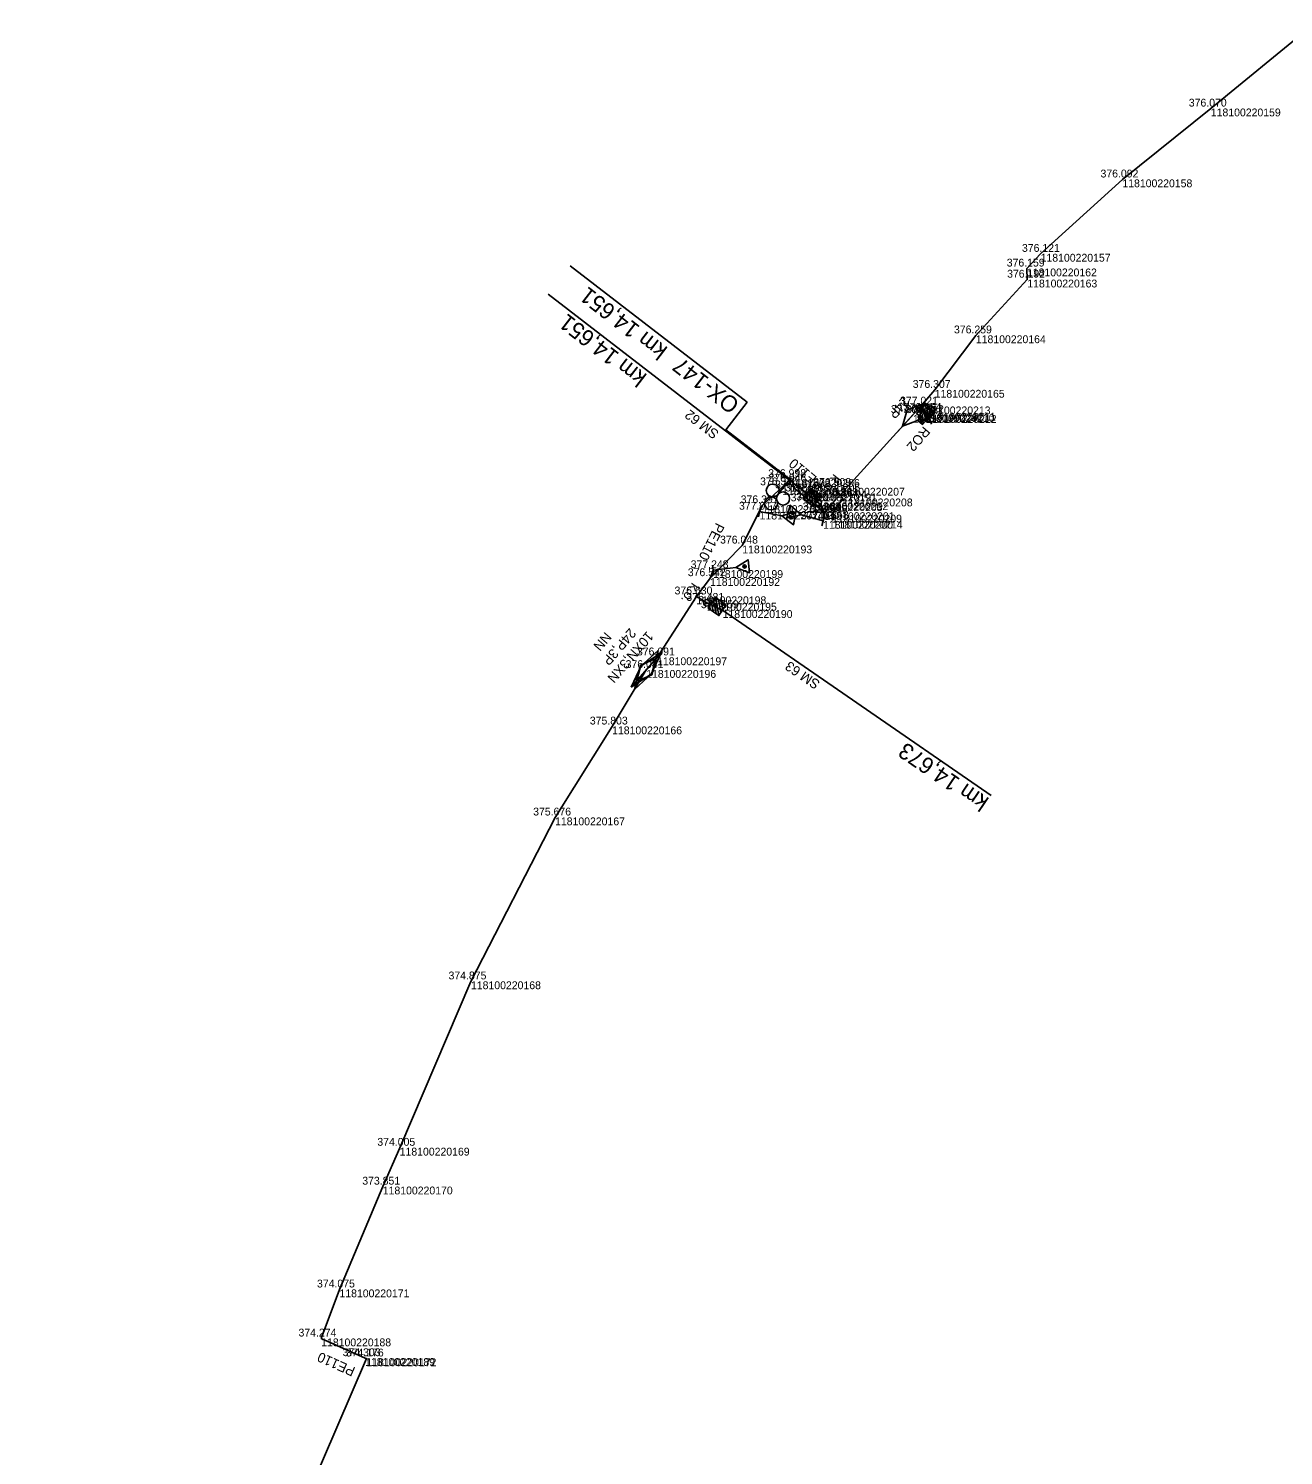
# Model space of a CAD drawing. Extents: x -732194 to -724760, y -944826 to -941477.
# Drawn here: x -730936.3 to -730744.2, y -941838.8 to -941620.2 of the extents above; entities that cross this region are included whole.
import ezdxf

# ---------------------------------------------------------------- set-up
doc = ezdxf.new("R2010")
doc.units = 0
for name, color, linetype in [('Vrstva 17', 7, 'Continuous'), ('Vrstva 25', 7, 'Continuous'), ('Vrstva 26', 7, 'Continuous'), ('Vrstva 28', 7, 'Continuous'), ('Vrstva 3', 7, 'Continuous'), ('Vrstva 31', 7, 'Continuous'), ('Vrstva 33', 7, 'Continuous'), ('Vrstva 35', 7, 'Continuous'), ('Vrstva 36', 7, 'Continuous'), ('Vrstva 4', 7, 'Continuous'), ('Vrstva 60', 7, 'Continuous'), ('Vrstva 61', 7, 'Continuous'), ('Vrstva 8', 7, 'Continuous')]:
    doc.layers.add(name, color=color, linetype=linetype)

msp = doc.modelspace()

# ---------------------------------------------------------------- linework, layer by layer
at = {"layer": 'Vrstva 17'}
msp.add_lwpolyline([(-730812.87, -941690.59), (-730811.67, -941692.23), (-730813.31, -941694.71), (-730813.21, -941695.61)], dxfattribs=at)
at = {"layer": 'Vrstva 25'}
msp.add_lwpolyline([(-730798.84, -941678.21), (-730798.08, -941678.86), (-730799.39, -941680.38), (-730800.15, -941679.72), (-730798.84, -941678.21)], dxfattribs=at)
at = {"layer": 'Vrstva 26'}
for points in [[(-730799.12, -941679.29), (-730799.74, -941678.13), (-730800.92, -941679.43), (-730814.44, -941694.33), (-730816.29, -941692.95), (-730818.68, -941690.96), (-730819.69, -941689.96), (-730820.94, -941690.5), (-730823.94, -941693.25), (-730827.05, -941699.43), (-730831.98, -941704.42), (-730834.08, -941707.22), (-730840.09, -941716.56), (-730841.76, -941718.5), (-730846.98, -941727.15), (-730855.72, -941741.09), (-730868.59, -941766.2), (-730879.51, -941791.69), (-730882.1, -941797.64), (-730888.73, -941813.4), (-730891.53, -941820.91), (-730884.81, -941823.92), (-730884.6, -941823.97), (-730893.54, -941844.74)], [(-730839.95, -941715.5), (-730840.91, -941719.02), (-730843.57, -941721.5), (-730842.62, -941717.98), (-730839.95, -941715.5)]]:
    msp.add_lwpolyline(points, dxfattribs=at)
at = {"layer": 'Vrstva 28'}
for p, q in [((-730798.58, -941676.84), (-730803.27, -941682.02)), ((-730801.79, -941678.65), (-730799.36, -941677.71)), ((-730799.36, -941677.71), (-730800.06, -941680.21)), ((-730802.49, -941681.15), (-730801.79, -941678.65)), ((-730800.06, -941680.21), (-730802.49, -941681.15)), ((-730800.16, -941680.16), (-730800.15, -941680.26)), ((-730799.8, -941679.77), (-730799.76, -941680.62)), ((-730799.74, -941678.13), (-730798.82, -941679.44)), ((-730799.44, -941679.38), (-730799.37, -941680.79)), ((-730799.09, -941678.98), (-730799.02, -941680.4)), ((-730798.73, -941678.59), (-730798.66, -941680)), ((-730798.37, -941678.2), (-730798.31, -941679.61)), ((-730798, -941678.16), (-730797.95, -941679.22)), ((-730797.61, -941678.52), (-730797.59, -941678.82)), ((-730819.69, -941689.96), (-730819.76, -941689.24)), ((-730823.94, -941693.25), (-730824.4, -941694.24)), ((-730815.39, -941692.77), (-730815.45, -941692.85)), ((-730814.44, -941694.33), (-730814.68, -941695.66)), ((-730831.98, -941704.42), (-730831.51, -941703.2)), ((-730832.44, -941708.17), (-730832.5, -941708.25)), ((-730844.04, -941721.15), (-730839.49, -941715.85)), ((-730842.64, -941717.74), (-730840.24, -941716.74)), ((-730840.24, -941716.74), (-730840.88, -941719.26)), ((-730843.28, -941720.27), (-730842.64, -941717.74)), ((-730840.88, -941719.26), (-730843.28, -941720.27))]:
    msp.add_line(p, q, dxfattribs=at)
for points in [[(-730814.44, -941694.33), (-730800.92, -941679.43), (-730799.74, -941678.13), (-730797.58, -941675.58), (-730791.28, -941667.23), (-730783.4, -941658.69), (-730783.46, -941656.99), (-730781.36, -941654.74), (-730768.84, -941643.34), (-730755.3, -941632.48), (-730740.34, -941620.23)], [(-730797.38, -941680.08), (-730798.45, -941679.77), (-730798.05, -941680.82)], [(-730834.08, -941707.22), (-730831.98, -941704.42), (-730827.05, -941699.43), (-730823.94, -941693.25), (-730820.94, -941690.5), (-730819.69, -941689.96), (-730818.68, -941690.96), (-730816.29, -941692.95), (-730814.44, -941694.33)], [(-730814.44, -941694.33), (-730815.42, -941692.81), (-730817.14, -941691.45)], [(-730936.34, -941912.8), (-730933.6, -941909.47), (-730918.42, -941890.11), (-730909.51, -941875.76), (-730901.25, -941861.12), (-730893.54, -941844.74), (-730884.6, -941823.97), (-730884.81, -941823.92), (-730891.53, -941820.91), (-730888.73, -941813.4), (-730882.1, -941797.64), (-730879.51, -941791.69), (-730868.59, -941766.2), (-730855.72, -941741.09), (-730846.98, -941727.15), (-730841.76, -941718.5), (-730840.09, -941716.56), (-730834.08, -941707.22), (-730832.47, -941708.21), (-730830.06, -941709.33)]]:
    msp.add_lwpolyline(points, dxfattribs=at)
msp.add_lwpolyline([(-730797.45, -941678.66), (-730799.46, -941680.88), (-730800.2, -941680.21), (-730798.19, -941677.99)], close=True, dxfattribs=at)
for centre in [(-730815.42, -941692.81), (-730832.47, -941708.21)]:
    msp.add_circle(centre, 0.5, dxfattribs=at)
at = {"layer": 'Vrstva 3'}
for p, q in [((-730856.75, -941660.93), (-730817.14, -941691.45)), ((-730816.59, -941693.14), (-730816.86, -941691.08)), ((-730816.17, -941693.47), (-730816.53, -941690.66)), ((-730815.85, -941693.05), (-730816.11, -941690.99)), ((-730817.43, -941692.5), (-730817.5, -941691.92)), ((-730817.01, -941692.82), (-730817.18, -941691.5)), ((-730815.52, -941692.63), (-730815.69, -941691.31)), ((-730815.2, -941692.21), (-730815.27, -941691.63)), ((-730831.75, -941708.26), (-730831.5, -941709.56)), ((-730831.45, -941707.82), (-730831.06, -941709.86)), ((-730831.15, -941707.38), (-730830.62, -941710.16)), ((-730830.71, -941707.68), (-730830.32, -941709.72)), ((-730830.27, -941707.98), (-730830.02, -941709.28)), ((-730829.83, -941708.27), (-730829.73, -941708.84)), ((-730832.04, -941708.7), (-730831.94, -941709.27)), ((-730788.92, -941737.75), (-730830.06, -941709.33))]:
    msp.add_line(p, q, dxfattribs=at)
for points in [[(-730817.75, -941692.25), (-730816.53, -941690.66), (-730814.95, -941691.88), (-730816.17, -941693.47)], [(-730829.5, -941708.5), (-730830.62, -941710.16), (-730832.27, -941709.04), (-730831.15, -941707.38)]]:
    msp.add_lwpolyline(points, close=True, dxfattribs=at)
at = {"layer": 'Vrstva 31'}
for points in [[(-730740.34, -941620.23), (-730755.3, -941632.48), (-730768.84, -941643.34), (-730781.36, -941654.74), (-730783.46, -941656.99), (-730783.4, -941658.69), (-730791.28, -941667.23), (-730797.58, -941675.58), (-730799.74, -941678.13), (-730798.95, -941679.08)], [(-730799.74, -941678.13), (-730800.92, -941679.43), (-730814.44, -941694.33), (-730816.29, -941692.95), (-730818.68, -941690.96), (-730819.69, -941689.96), (-730820.94, -941690.5), (-730823.94, -941693.25), (-730827.05, -941699.43), (-730831.98, -941704.42), (-730834.08, -941707.22), (-730840.09, -941716.56), (-730841.76, -941718.5), (-730846.98, -941727.15), (-730855.72, -941741.09), (-730868.59, -941766.2), (-730879.51, -941791.69), (-730882.1, -941797.64), (-730888.73, -941813.4), (-730891.53, -941820.91), (-730884.81, -941823.92), (-730884.6, -941823.97), (-730893.54, -941844.74)], [(-730844.04, -941721.15), (-730842.52, -941717.85), (-730839.48, -941715.85), (-730841, -941719.15), (-730844.04, -941721.15)]]:
    msp.add_lwpolyline(points, dxfattribs=at)
at = {"layer": 'Vrstva 33'}
for p, q in [((-730798.57, -941679.41), (-730799.33, -941678.76)), ((-730798.24, -941679.03), (-730798.9, -941679.79))]:
    msp.add_line(p, q, dxfattribs=at)
msp.add_lwpolyline([(-730797.54, -941678.98), (-730798.85, -941680.5), (-730800.36, -941679.19), (-730799.05, -941677.67), (-730797.54, -941678.98)], dxfattribs=at)
at = {"layer": 'Vrstva 35'}
for p, q in [((-730818.68, -941690.96), (-730816.29, -941692.95)), ((-730891.53, -941820.91), (-730884.81, -941823.92))]:
    msp.add_line(p, q, dxfattribs=at)
msp.add_lwpolyline([(-730831.98, -941704.42), (-730827.05, -941699.43), (-730823.94, -941693.25), (-730820.94, -941690.5)], dxfattribs=at)
at = {"layer": 'Vrstva 4'}
for p, q in [((-730824.25, -941693.48), (-730824.55, -941695.01)), ((-730819.77, -941694.91), (-730819.5, -941695.31)), ((-730819.24, -941694.63), (-730819.48, -941694.21)), ((-730814.88, -941696.41), (-730814.47, -941694.91)), ((-730831.59, -941702.42), (-730831.42, -941703.97)), ((-730826.89, -941702.48), (-730826.51, -941702.79))]:
    msp.add_line(p, q, dxfattribs=at)
for points in [[(-730814.68, -941695.66), (-730818.03, -941694.75), (-730820.23, -941695.18), (-730819.71, -941693.25), (-730818.03, -941694.75)], [(-730824.4, -941694.24), (-730820.98, -941694.89), (-730818.83, -941694.29), (-730819.19, -941696.25), (-730820.98, -941694.89)], [(-730831.51, -941703.2), (-730828.05, -941702.82), (-730826.16, -941701.62), (-730825.94, -941703.6), (-730828.05, -941702.82)]]:
    msp.add_lwpolyline(points, dxfattribs=at)
for centre in [(-730819.64, -941695.11), (-730819.36, -941694.42), (-730826.7, -941702.64)]:
    msp.add_circle(centre, 0.248, dxfattribs=at)
at = {"layer": 'Vrstva 60'}
for p, q in [((-730755.3, -941632.48), (-730755.3, -941632.48)), ((-730768.84, -941643.34), (-730768.84, -941643.34)), ((-730781.36, -941654.74), (-730781.36, -941654.74)), ((-730783.46, -941656.99), (-730783.46, -941656.99)), ((-730783.4, -941658.69), (-730783.4, -941658.69)), ((-730791.28, -941667.23), (-730791.28, -941667.23)), ((-730797.58, -941675.58), (-730797.58, -941675.58)), ((-730800.92, -941679.43), (-730800.92, -941679.43)), ((-730799.74, -941678.13), (-730799.74, -941678.13)), ((-730799.12, -941679.29), (-730799.12, -941679.29)), ((-730798.95, -941679.08), (-730798.95, -941679.08)), ((-730798.82, -941679.44), (-730798.82, -941679.44)), ((-730820.94, -941690.5), (-730820.94, -941690.5)), ((-730819.76, -941689.24), (-730819.76, -941689.24)), ((-730819.69, -941689.96), (-730819.69, -941689.96)), ((-730818.68, -941690.96), (-730818.68, -941690.96)), ((-730812.87, -941690.59), (-730812.87, -941690.59)), ((-730823.94, -941693.25), (-730823.94, -941693.25)), ((-730817.14, -941691.45), (-730817.14, -941691.45)), ((-730816.29, -941692.95), (-730816.29, -941692.95)), ((-730815.42, -941692.81), (-730815.42, -941692.81)), ((-730811.67, -941692.23), (-730811.67, -941692.23)), ((-730824.4, -941694.24), (-730824.4, -941694.24)), ((-730814.44, -941694.33), (-730814.44, -941694.33)), ((-730813.31, -941694.71), (-730813.31, -941694.71)), ((-730814.68, -941695.66), (-730814.68, -941695.66)), ((-730813.21, -941695.61), (-730813.21, -941695.61)), ((-730827.05, -941699.43), (-730827.05, -941699.43)), ((-730831.51, -941703.2), (-730831.51, -941703.2)), ((-730831.98, -941704.42), (-730831.98, -941704.42)), ((-730834.08, -941707.22), (-730834.08, -941707.22)), ((-730832.47, -941708.21), (-730832.47, -941708.21)), ((-730830.06, -941709.33), (-730830.06, -941709.33)), ((-730840.09, -941716.56), (-730840.09, -941716.56)), ((-730841.76, -941718.5), (-730841.76, -941718.5)), ((-730846.98, -941727.15), (-730846.98, -941727.15)), ((-730855.72, -941741.09), (-730855.72, -941741.09)), ((-730868.59, -941766.2), (-730868.59, -941766.2)), ((-730879.51, -941791.69), (-730879.51, -941791.69)), ((-730882.1, -941797.64), (-730882.1, -941797.64)), ((-730888.73, -941813.4), (-730888.73, -941813.4)), ((-730891.53, -941820.91), (-730891.53, -941820.91)), ((-730884.81, -941823.92), (-730884.81, -941823.92)), ((-730884.6, -941823.97), (-730884.6, -941823.97))]:
    msp.add_line(p, q, dxfattribs=at)
at = {"layer": 'Vrstva 8'}
for p, q in [((-730853.38, -941656.56), (-730826.28, -941677.45)), ((-730819.17, -941689.7), (-730820.36, -941688.79)), ((-730819.76, -941689.24), (-730821.59, -941691.62))]:
    msp.add_line(p, q, dxfattribs=at)
msp.add_lwpolyline([(-730826.28, -941677.45), (-730829.55, -941681.7), (-730819.76, -941689.24)], dxfattribs=at)
for centre in [(-730822.38, -941691.01), (-730822.63, -941692.97), (-730820.8, -941692.23)]:
    msp.add_circle(centre, 1, dxfattribs=at)

# ---------------------------------------------------------------- texts
at = {"layer": 'Vrstva 25'}
msp.add_text('RO2', height=1.5, rotation=229.1993, dxfattribs=at).set_placement((-730799.28, -941681.07))
at = {"layer": 'Vrstva 26'}
msp.add_text('NN', height=1.5, rotation=229.2994, dxfattribs=at).set_placement((-730848.07, -941712.56))
at = {"layer": 'Vrstva 28'}
for s, rotation, p in [('24P', 227.7809, (-730802.38, -941676.49)), ('k.o.', 232.3797, (-730813.03, -941688.37)), ('k.o.', 235.8719, (-730834.7, -941705.03)), ('24P,3P', 229.2994, (-730844.3, -941711.98))]:
    msp.add_text(s, height=1.5, rotation=rotation, dxfattribs=at).set_placement(p)
at = {"layer": 'Vrstva 3'}
for s, height, rotation, p in [('km 14,651', 2.5, 142.3797, (-730841.48, -941673.33)), ('SM 62', 1.5, 142.3797, (-730830.5, -941682.05)), ('SM 63', 1.5, 145.8719, (-730815.01, -941720.32)), ('km 14,673', 2.5, 145.8719, (-730789.09, -941738.24))]:
    msp.add_text(s, height=height, rotation=rotation, dxfattribs=at).set_placement(p)
at = {"layer": 'Vrstva 31'}
msp.add_text('10XN,3XN', height=1.5, rotation=229.2994, dxfattribs=at).set_placement((-730841.63, -941712.46))
at = {"layer": 'Vrstva 36'}
for rotation, p in [(140.2086, (-730814.48, -941689.84)), (243.2757, (-730831.04, -941695.83)), (155.8905, (-730886.18, -941825.41))]:
    msp.add_text('PE110', height=1.5, rotation=rotation, dxfattribs=at).set_placement(p)
at = {"layer": 'Vrstva 60'}
for s, p in [('118100220159', (-730755.3, -941633.68)), ('118100220158', (-730768.84, -941644.54)), ('118100220157', (-730781.36, -941655.94)), ('118100220162', (-730783.46, -941658.19)), ('118100220163', (-730783.4, -941659.89)), ('118100220164', (-730791.28, -941668.43)), ('118100220165', (-730797.58, -941676.78)), ('118100220241', (-730800.92, -941680.63)), ('118100220213', (-730799.74, -941679.33)), ('118100220210', (-730799.12, -941680.49)), ('118100220211', (-730798.95, -941680.29)), ('118100220212', (-730798.82, -941680.64)), ('118100220194', (-730820.94, -941691.7)), ('118100220206', (-730819.76, -941690.44)), ('118100220205', (-730819.69, -941691.16)), ('118100220204', (-730818.68, -941692.17)), ('118100220207', (-730812.87, -941691.79)), ('118100220239', (-730823.94, -941694.45)), ('118100220191', (-730817.14, -941692.65)), ('118100220203', (-730816.29, -941694.15)), ('118100220202', (-730815.42, -941694.01)), ('118100220208', (-730811.67, -941693.43)), ('118100220240', (-730824.4, -941695.44)), ('118100220201', (-730814.44, -941695.53)), ('118100220209', (-730813.31, -941695.91)), ('118100220200', (-730814.68, -941696.86)), ('118100220214', (-730813.21, -941696.81)), ('118100220193', (-730827.05, -941700.63)), ('118100220199', (-730831.51, -941704.4)), ('118100220192', (-730831.98, -941705.62)), ('118100220198', (-730834.08, -941708.42)), ('118100220195', (-730832.47, -941709.41)), ('118100220190', (-730830.06, -941710.53)), ('118100220197', (-730840.09, -941717.76)), ('118100220196', (-730841.76, -941719.7)), ('118100220166', (-730846.98, -941728.35)), ('118100220167', (-730855.72, -941742.29)), ('118100220168', (-730868.59, -941767.4)), ('118100220169', (-730879.51, -941792.89)), ('118100220170', (-730882.1, -941798.84)), ('118100220171', (-730888.73, -941814.6)), ('118100220188', (-730891.53, -941822.11)), ('118100220189', (-730884.81, -941825.12)), ('118100220172', (-730884.6, -941825.17))]:
    msp.add_text(s, height=1.2, dxfattribs=at).set_placement(p)
at = {"layer": 'Vrstva 61'}
for s, p in [('376.070', (-730758.67, -941632.18)), ('376.092', (-730772.19, -941643.04)), ('376.121', (-730784.22, -941654.44)), ('376.159', (-730786.55, -941656.69)), ('376.192', (-730786.49, -941658.39)), ('376.259', (-730794.63, -941666.93)), ('376.307', (-730800.95, -941675.28)), ('377.009', (-730804.3, -941679.13)), ('377.021', (-730802.89, -941677.83)), ('376.954', (-730802.33, -941678.79)), ('376.951', (-730802.21, -941678.99)), ('377.012', (-730801.97, -941679.14)), ('376.998', (-730823.08, -941688.94)), ('376.946', (-730823.04, -941689.66)), ('376.375', (-730824.32, -941690.2)), ('376.597', (-730822.03, -941690.67)), ('376.766', (-730820.47, -941691.15)), ('376.909', (-730816.19, -941690.29)), ('376.864', (-730815.05, -941691.93)), ('377.017', (-730827.55, -941693.94)), ('376.397', (-730827.29, -941692.95)), ('376.529', (-730819.64, -941692.65)), ('376.953', (-730818.78, -941692.51)), ('376.868', (-730817.79, -941694.03)), ('376.848', (-730816.71, -941694.41)), ('377.020', (-730818.08, -941695.36)), ('376.868', (-730816.56, -941695.31)), ('376.048', (-730830.45, -941699.13)), ('377.248', (-730834.95, -941702.9)), ('376.542', (-730835.39, -941704.12)), ('376.630', (-730837.42, -941706.92)), ('376.481', (-730835.62, -941707.91)), ('376.659', (-730833.38, -941709.03)), ('376.091', (-730843.18, -941716.26)), ('376.041', (-730844.91, -941718.2)), ('375.803', (-730850.39, -941726.85)), ('375.676', (-730859.07, -941740.79)), ('374.875', (-730872.03, -941765.9)), ('374.005', (-730882.93, -941791.39)), ('373.851', (-730885.24, -941797.34)), ('374.075', (-730892.17, -941813.1)), ('374.274', (-730895, -941820.61)), ('374.303', (-730888.24, -941823.62)), ('374.176', (-730887.76, -941823.67))]:
    msp.add_text(s, height=1.2, dxfattribs=at).set_placement(p)
at = {"layer": 'Vrstva 8'}
for s, p in [('km 14,651', (-730838.31, -941669.2)), ('OX-147', (-730827.29, -941677.46))]:
    msp.add_text(s, height=2.5, rotation=142.3797, dxfattribs=at).set_placement(p)

doc.saveas('drawing.dxf')
